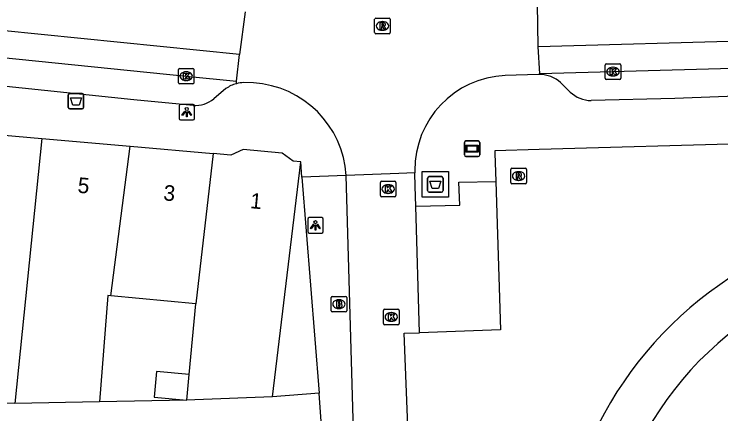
# Model space of a CAD drawing. Extents: x 162250 to 162654, y 380744 to 381605.
# Drawn here: x 162347.75 to 162393.23, y 381182.3 to 381208.05 of the extents above; entities that cross this region are included whole.
import ezdxf

# ---------------------------------------------------------------- set-up
doc = ezdxf.new("R2010")
doc.units = 0
for name, color, linetype in [('IMGEO_Afval_apart_plaats', 7, 'Continuous'), ('IMGEO_Afvalbak', 7, 'Continuous'), ('IMGEO_Brandkraan', 7, 'Continuous'), ('IMGEO_Kolk', 7, 'Continuous'), ('IMGEO_Lichtpunt', 7, 'Continuous'), ('IMGEO_Pand', 7, 'Continuous'), ('IMGEO_Pand_nummerreeks', 7, 'Continuous'), ('IMGEO_Parkeervlak_open', 7, 'Continuous'), ('IMGEO_Reclamebord', 7, 'Continuous'), ('IMGEO_Rijbaan_lokaal_gesloten', 7, 'Continuous'), ('IMGEO_Rioolput', 7, 'Continuous'), ('IMGEO_Voetpad_gesloten', 7, 'Continuous'), ('IMGEO_Voetpad_open', 7, 'Continuous'), ('IMGEO_Woonerf_open', 7, 'Continuous')]:
    doc.layers.add(name, color=color, linetype=linetype)

msp = doc.modelspace()

# ---------------------------------------------------------------- linework, layer by layer
at = {"layer": 'IMGEO_Afval_apart_plaats'}
for p, q in [((162374.461, 381197.584), (162375.251, 381197.584)), ((162375.251, 381197.584), (162374.461, 381197.584)), ((162374.361, 381196.684), (162374.361, 381197.484)), ((162374.361, 381197.484), (162374.361, 381196.684)), ((162375.351, 381197.484), (162375.351, 381196.684)), ((162375.351, 381196.684), (162375.351, 381197.484)), ((162375.251, 381196.584), (162374.461, 381196.584)), ((162374.461, 381196.584), (162375.251, 381196.584))]:
    msp.add_line(p, q, dxfattribs=at)
msp.add_lwpolyline([(162374.504, 381197.298), (162375.208, 381197.298), (162375.059, 381196.828), (162374.653, 381196.828), (162374.504, 381197.298)], dxfattribs=at)
for centre, start, end in [((162374.461, 381197.484), 90, 180), ((162374.461, 381197.484), 90, 180), ((162375.251, 381197.484), 0, 90), ((162375.251, 381197.484), 360, 90), ((162374.461, 381196.684), 180, 270), ((162374.461, 381196.684), 180, 270), ((162375.251, 381196.684), 270, 0), ((162375.251, 381196.684), 270, 0)]:
    msp.add_arc(centre, 0.1, start, end, dxfattribs=at)
at = {"layer": 'IMGEO_Afvalbak'}
for p, q in [((162351.23, 381202.041), (162351.23, 381202.841)), ((162351.23, 381202.841), (162351.23, 381202.041)), ((162351.33, 381202.941), (162352.12, 381202.941)), ((162352.12, 381202.941), (162351.33, 381202.941)), ((162352.22, 381202.841), (162352.22, 381202.041)), ((162352.22, 381202.041), (162352.22, 381202.841)), ((162352.12, 381201.941), (162351.33, 381201.941)), ((162351.33, 381201.941), (162352.12, 381201.941))]:
    msp.add_line(p, q, dxfattribs=at)
msp.add_lwpolyline([(162351.373, 381202.655), (162352.077, 381202.655), (162351.928, 381202.185), (162351.522, 381202.185), (162351.373, 381202.655)], dxfattribs=at)
for centre, start, end in [((162351.33, 381202.841), 90, 180), ((162351.33, 381202.841), 90, 180), ((162352.12, 381202.841), 0, 90), ((162352.12, 381202.841), 360, 90), ((162351.33, 381202.041), 180, 270), ((162351.33, 381202.041), 180, 270), ((162352.12, 381202.041), 270, 0), ((162352.12, 381202.041), 270, 0)]:
    msp.add_arc(centre, 0.1, start, end, dxfattribs=at)
at = {"layer": 'IMGEO_Brandkraan'}
for p, q in [((162368.148, 381188.942), (162368.148, 381189.794)), ((162368.223, 381189.868), (162369.075, 381189.868)), ((162369.149, 381189.794), (162369.149, 381188.942)), ((162368.636, 381189.648), (162368.661, 381189.648)), ((162368.659, 381189.088), (162368.634, 381189.088)), ((162369.075, 381188.868), (162368.223, 381188.868))]:
    msp.add_line(p, q, dxfattribs=at)
for points in [[(162368.148, 381188.942), (162368.148, 381189.794)], [(162368.223, 381189.868), (162369.075, 381189.868)], [(162369.149, 381189.794), (162369.149, 381188.942)], [(162368.496, 381189.568), (162368.496, 381189.168), (162368.709, 381189.168)], [(162368.727, 381189.568), (162368.496, 381189.568)], [(162368.675, 381189.487), (162368.621, 381189.487), (162368.621, 381189.411)], [(162368.621, 381189.411), (162368.674, 381189.411)], [(162368.683, 381189.335), (162368.621, 381189.335), (162368.621, 381189.254)], [(162368.621, 381189.254), (162368.683, 381189.254)], [(162369.075, 381188.868), (162368.223, 381188.868)]]:
    msp.add_lwpolyline(points, dxfattribs=at)
for centre, radius, start, end in [((162368.225, 381189.792), 0.0765, 91.552, 178.448), ((162368.225, 381189.792), 0.0765, 91.552, 178.448), ((162369.073, 381189.792), 0.0765, 1.552, 88.448), ((162369.073, 381189.792), 0.0765, 1.552, 88.448), ((162368.676, 381189.449), 0.0379, 267.8285, 90.9355), ((162368.684, 381189.294), 0.0404, 269.8759, 90.5077), ((162368.731, 381189.423), 0.145, 59.4692, 91.5367), ((162368.756, 381189.47), 0.0922, 285.5137, 58.1501), ((162368.761, 381189.278), 0.105, 301.3115, 78.989), ((162368.225, 381188.944), 0.0765, 181.552, 268.448), ((162368.225, 381188.944), 0.0765, 181.552, 268.448), ((162368.715, 381189.419), 0.251, 268.6676, 293.5347), ((162369.073, 381188.944), 0.0765, 271.552, 358.448), ((162369.073, 381188.944), 0.0765, 271.552, 358.448)]:
    msp.add_arc(centre, radius, start, end, dxfattribs=at)
for centre, major_axis, ratio, start_param, end_param in [((162368.635, 381189.368), (-0.387, 0.002), 0.722429, 4.712389, 7.853982), ((162368.66, 381189.368), (-0.39, 0.002), 0.717154, 1.570796, 4.712389)]:
    msp.add_ellipse(centre, major_axis=major_axis, ratio=ratio, start_param=start_param, end_param=end_param, dxfattribs=at)
at = {"layer": 'IMGEO_Kolk'}
for p, q in [((162385.861, 381204.847), (162386.713, 381204.847)), ((162358.322, 381203.627), (162358.322, 381204.479)), ((162358.397, 381204.553), (162359.249, 381204.553)), ((162359.323, 381204.479), (162359.323, 381203.627)), ((162385.786, 381203.921), (162385.786, 381204.773)), ((162386.274, 381204.627), (162386.299, 381204.627)), ((162386.787, 381204.773), (162386.787, 381203.921)), ((162358.81, 381204.333), (162358.835, 381204.333)), ((162386.297, 381204.067), (162386.272, 381204.067)), ((162359.249, 381203.553), (162358.397, 381203.553)), ((162358.833, 381203.773), (162358.808, 381203.773)), ((162386.713, 381203.847), (162385.861, 381203.847)), ((162371.321, 381196.357), (162371.321, 381197.209)), ((162371.396, 381197.283), (162372.248, 381197.283)), ((162371.809, 381197.063), (162371.834, 381197.063)), ((162372.322, 381197.209), (162372.322, 381196.357)), ((162372.248, 381196.283), (162371.396, 381196.283)), ((162371.832, 381196.503), (162371.807, 381196.503)), ((162371.517, 381188.116), (162371.517, 381188.968)), ((162371.592, 381189.042), (162372.444, 381189.042)), ((162372.518, 381188.968), (162372.518, 381188.116)), ((162372.005, 381188.822), (162372.03, 381188.822)), ((162372.444, 381188.042), (162371.592, 381188.042)), ((162372.028, 381188.262), (162372.003, 381188.262))]:
    msp.add_line(p, q, dxfattribs=at)
for points in [[(162385.861, 381204.847), (162386.713, 381204.847)], [(162358.322, 381203.627), (162358.322, 381204.479)], [(162358.397, 381204.553), (162359.249, 381204.553)], [(162359.323, 381204.479), (162359.323, 381203.627)], [(162385.786, 381203.921), (162385.786, 381204.773)], [(162386.107, 381204.547), (162386.23, 381204.547), (162386.23, 381204.396), (162386.36, 381204.547), (162386.524, 381204.547), (162386.378, 381204.396), (162386.531, 381204.147), (162386.379, 381204.147), (162386.294, 381204.311), (162386.23, 381204.244), (162386.23, 381204.147), (162386.107, 381204.147), (162386.107, 381204.547)], [(162386.787, 381204.773), (162386.787, 381203.921)], [(162358.643, 381204.253), (162358.766, 381204.253), (162358.766, 381204.102), (162358.896, 381204.253), (162359.06, 381204.253), (162358.914, 381204.102), (162359.067, 381203.853), (162358.915, 381203.853), (162358.83, 381204.017), (162358.766, 381203.95), (162358.766, 381203.853), (162358.643, 381203.853), (162358.643, 381204.253)], [(162359.249, 381203.553), (162358.397, 381203.553)], [(162386.713, 381203.847), (162385.861, 381203.847)], [(162371.321, 381196.357), (162371.321, 381197.209)], [(162371.396, 381197.283), (162372.248, 381197.283)], [(162372.322, 381197.209), (162372.322, 381196.357)], [(162371.642, 381196.983), (162371.765, 381196.983), (162371.765, 381196.832), (162371.895, 381196.983), (162372.059, 381196.983), (162371.913, 381196.832), (162372.066, 381196.583), (162371.914, 381196.583), (162371.829, 381196.747), (162371.765, 381196.68), (162371.765, 381196.583), (162371.642, 381196.583), (162371.642, 381196.983)], [(162372.248, 381196.283), (162371.396, 381196.283)], [(162371.517, 381188.116), (162371.517, 381188.968)], [(162371.592, 381189.042), (162372.444, 381189.042)], [(162372.518, 381188.968), (162372.518, 381188.116)], [(162371.838, 381188.742), (162371.961, 381188.742), (162371.961, 381188.591), (162372.091, 381188.742), (162372.255, 381188.742), (162372.109, 381188.591), (162372.262, 381188.342), (162372.11, 381188.342), (162372.025, 381188.506), (162371.961, 381188.439), (162371.961, 381188.342), (162371.838, 381188.342), (162371.838, 381188.742)], [(162372.444, 381188.042), (162371.592, 381188.042)]]:
    msp.add_lwpolyline(points, dxfattribs=at)
for centre, start, end in [((162385.863, 381204.771), 91.552, 178.448), ((162385.863, 381204.771), 91.552, 178.448), ((162386.711, 381204.771), 1.552, 88.448), ((162386.711, 381204.771), 1.552, 88.448), ((162358.399, 381204.477), 91.552, 178.448), ((162358.399, 381204.477), 91.552, 178.448), ((162359.247, 381204.477), 1.552, 88.448), ((162359.247, 381204.477), 1.552, 88.448), ((162385.863, 381203.923), 181.552, 268.448), ((162385.863, 381203.923), 181.552, 268.448), ((162386.711, 381203.923), 271.552, 358.448), ((162386.711, 381203.923), 271.552, 358.448), ((162358.399, 381203.629), 181.552, 268.448), ((162358.399, 381203.629), 181.552, 268.448), ((162359.247, 381203.629), 271.552, 358.448), ((162359.247, 381203.629), 271.552, 358.448), ((162371.398, 381197.207), 91.552, 178.448), ((162371.398, 381197.207), 91.552, 178.448), ((162372.246, 381197.207), 1.552, 88.448), ((162372.246, 381197.207), 1.552, 88.448), ((162371.398, 381196.359), 181.552, 268.448), ((162371.398, 381196.359), 181.552, 268.448), ((162372.246, 381196.359), 271.552, 358.448), ((162372.246, 381196.359), 271.552, 358.448), ((162371.594, 381188.966), 91.552, 178.448), ((162371.594, 381188.966), 91.552, 178.448), ((162372.442, 381188.966), 1.552, 88.448), ((162372.442, 381188.966), 1.552, 88.448), ((162371.594, 381188.118), 181.552, 268.448), ((162371.594, 381188.118), 181.552, 268.448), ((162372.442, 381188.118), 271.552, 358.448), ((162372.442, 381188.118), 271.552, 358.448)]:
    msp.add_arc(centre, 0.0765, start, end, dxfattribs=at)
for centre, major_axis, ratio, start_param, end_param in [((162386.273, 381204.347), (-0.387, 0.002), 0.722429, 4.712389, 7.853982), ((162386.298, 381204.347), (-0.39, 0.002), 0.717154, 1.570796, 4.712389), ((162358.809, 381204.053), (-0.387, 0.002), 0.722429, 4.712389, 7.853982), ((162358.834, 381204.053), (-0.39, 0.002), 0.717154, 1.570796, 4.712389), ((162371.808, 381196.783), (-0.387, 0.002), 0.722429, 4.712389, 7.853982), ((162371.833, 381196.783), (-0.39, 0.002), 0.717154, 1.570796, 4.712389), ((162372.004, 381188.542), (-0.387, 0.002), 0.722429, 4.712389, 7.853982), ((162372.029, 381188.542), (-0.39, 0.002), 0.717154, 1.570796, 4.712389)]:
    msp.add_ellipse(centre, major_axis=major_axis, ratio=ratio, start_param=start_param, end_param=end_param, dxfattribs=at)
at = {"layer": 'IMGEO_Lichtpunt'}
for p, q in [((162358.359, 381202.144), (162358.359, 381201.337)), ((162358.359, 381202.144), (162358.359, 381201.337)), ((162359.261, 381202.239), (162358.453, 381202.239)), ((162359.261, 381202.239), (162358.453, 381202.239)), ((162359.355, 381201.337), (162359.355, 381202.144)), ((162359.355, 381201.337), (162359.355, 381202.144)), ((162358.453, 381201.243), (162359.261, 381201.243)), ((162358.453, 381201.243), (162359.261, 381201.243)), ((162366.64, 381194.85), (162366.64, 381194.043)), ((162366.64, 381194.85), (162366.64, 381194.043)), ((162367.542, 381194.945), (162366.734, 381194.945)), ((162367.542, 381194.945), (162366.734, 381194.945)), ((162367.636, 381194.043), (162367.636, 381194.85)), ((162367.636, 381194.043), (162367.636, 381194.85)), ((162366.734, 381193.949), (162367.542, 381193.949)), ((162366.734, 381193.949), (162367.542, 381193.949))]:
    msp.add_line(p, q, dxfattribs=at)
for points in [[(162358.733, 381201.808), (162358.772, 381201.78), (162358.584, 381201.518), (162358.546, 381201.545), (162358.733, 381201.808)], [(162358.835, 381201.76), (162358.882, 381201.76), (162358.882, 381201.438), (162358.835, 381201.438), (162358.835, 381201.76)], [(162358.945, 381201.78), (162358.983, 381201.807), (162359.17, 381201.545), (162359.131, 381201.517), (162358.945, 381201.78)], [(162367.014, 381194.514), (162367.053, 381194.486), (162366.865, 381194.224), (162366.827, 381194.251), (162367.014, 381194.514)], [(162367.116, 381194.466), (162367.163, 381194.466), (162367.163, 381194.144), (162367.116, 381194.144), (162367.116, 381194.466)], [(162367.226, 381194.486), (162367.264, 381194.513), (162367.451, 381194.251), (162367.412, 381194.223), (162367.226, 381194.486)]]:
    msp.add_lwpolyline(points, dxfattribs=at)
for centre in [(162358.858, 381201.942), (162367.139, 381194.648)]:
    msp.add_circle(centre, 0.0994, dxfattribs=at)
for centre, start, end in [((162358.453, 381202.144), 90, 180), ((162358.453, 381202.144), 90, 180), ((162359.261, 381202.144), 0, 90), ((162359.261, 381202.144), 0, 90), ((162358.453, 381201.337), 180, 270), ((162358.453, 381201.337), 180, 270), ((162359.261, 381201.337), 270, 0), ((162359.261, 381201.337), 270, 360), ((162366.734, 381194.85), 90, 180), ((162366.734, 381194.85), 90, 180), ((162367.542, 381194.85), 0, 90), ((162367.542, 381194.85), 0, 90), ((162366.734, 381194.043), 180, 270), ((162366.734, 381194.043), 180, 270), ((162367.542, 381194.043), 270, 0), ((162367.542, 381194.043), 270, 360)]:
    msp.add_arc(centre, 0.0946, start, end, dxfattribs=at)
at = {"layer": 'IMGEO_Pand'}
for points in [[(162344.185, 381200.52), (162349.528, 381200.046)], [(162349.528, 381200.046), (162347.792, 381182.966)], [(162349.528, 381200.046), (162355.226, 381199.54)], [(162353.981, 381189.903), (162355.226, 381199.54)], [(162355.226, 381199.54), (162360.555, 381199.068)], [(162360.555, 381199.068), (162359.44, 381189.386)], [(162366.19, 381198.541), (162365.705, 381198.587), (162364.991, 381199.094), (162362.485, 381199.331), (162361.691, 381198.967), (162360.555, 381199.068)], [(162364.374, 381183.398), (162366.19, 381198.541)], [(162353.981, 381189.903), (162353.771, 381189.923), (162353.232, 381183.071)], [(162359.44, 381189.386), (162353.981, 381189.903)], [(162359.013, 381184.831), (162359.44, 381189.386)], [(162359.013, 381184.831), (162356.905, 381185.029), (162356.75, 381183.375), (162358.859, 381183.183)], [(162358.859, 381183.183), (162359.013, 381184.831)], [(162347.792, 381182.966), (162342.165, 381183.123)], [(162353.232, 381183.071), (162347.792, 381182.966)], [(162364.374, 381183.398), (162359.378, 381183.203), (162358.859, 381183.183)]]:
    msp.add_lwpolyline(points, dxfattribs=at)
at = {"layer": 'IMGEO_Parkeervlak_open'}
for points in [[(162378.745, 381197.276), (162379.047, 381187.724), (162373.842, 381187.531)], [(162373.842, 381187.531), (162373.596, 381195.687)]]:
    msp.add_lwpolyline(points, dxfattribs=at)
at = {"layer": 'IMGEO_Reclamebord'}
for p, q in [((162376.825, 381199.881), (162377.615, 381199.881)), ((162377.615, 381199.881), (162376.825, 381199.881)), ((162376.725, 381198.981), (162376.725, 381199.781)), ((162376.725, 381199.781), (162376.725, 381198.981)), ((162377.715, 381199.781), (162377.715, 381198.981)), ((162377.715, 381198.981), (162377.715, 381199.781)), ((162377.615, 381198.881), (162376.825, 381198.881)), ((162376.825, 381198.881), (162377.615, 381198.881))]:
    msp.add_line(p, q, dxfattribs=at)
for points in [[(162376.826, 381199.613), (162377.614, 381199.613), (162377.614, 381199.149), (162376.826, 381199.149), (162376.826, 381199.613)], [(162376.891, 381199.548), (162376.891, 381199.214), (162377.549, 381199.214), (162377.549, 381199.548), (162376.891, 381199.548)]]:
    msp.add_lwpolyline(points, dxfattribs=at)
for centre, start, end in [((162376.825, 381199.781), 90, 180), ((162376.825, 381199.781), 90, 180), ((162377.615, 381199.781), 0, 90), ((162377.615, 381199.781), 360, 90), ((162376.825, 381198.981), 180, 270), ((162376.825, 381198.981), 180, 270), ((162377.615, 381198.981), 270, 0), ((162377.615, 381198.981), 270, 0)]:
    msp.add_arc(centre, 0.1, start, end, dxfattribs=at)
at = {"layer": 'IMGEO_Rijbaan_lokaal_gesloten'}
for points in [[(162362.253, 381205.457), (162329.041, 381208.801), (162327.697, 381208.936)], [(162381.477, 381205.975), (162381.43, 381208.683)], [(162362.607, 381208.202), (162362.253, 381205.457)], [(162381.477, 381205.975), (162409.05, 381206.74), (162411.31, 381206.802), (162453.911, 381207.983)], [(162325.166, 381207.213), (162334.8, 381206.462), (162345.523, 381205.417), (162358.828, 381204.054), (162362.066, 381203.727)], [(162381.577, 381204.213), (162381.477, 381205.975)], [(162362.066, 381203.727), (162362.253, 381205.457)], [(162409.861, 381205.082), (162401.103, 381204.745), (162399.402, 381204.708), (162381.577, 381204.213)], [(162381.579, 381204.167), (162381.515, 381204.168), (162381.488, 381204.167), (162379.35, 381204.095)], [(162381.577, 381204.213), (162381.579, 381204.167)], [(162362.049, 381203.571), (162362.066, 381203.727)], [(162363.148, 381203.617), (162362.523, 381203.642)], [(162373.543, 381197.824), (162372.496, 381197.784), (162369.115, 381197.654)], [(162373.541, 381197.966), (162373.543, 381197.824)]]:
    msp.add_lwpolyline(points, dxfattribs=at)
for centre, radius, start, end in [((162379.607, 381198.034), 6.067, 92.4325, 180.6384), ((162362.597, 381201.532), 2.111, 92.0002, 105.0377), ((162362.775, 381197.277), 6.351, 3.4038, 86.6346)]:
    msp.add_arc(centre, radius, start, end, dxfattribs=at)
at = {"layer": 'IMGEO_Rioolput'}
for p, q in [((162370.95, 381206.863), (162370.95, 381207.715)), ((162371.025, 381207.789), (162371.877, 381207.789)), ((162371.438, 381207.569), (162371.463, 381207.569)), ((162371.951, 381207.715), (162371.951, 381206.863)), ((162371.877, 381206.789), (162371.025, 381206.789)), ((162371.461, 381207.009), (162371.436, 381207.009)), ((162379.713, 381197.195), (162379.713, 381198.047)), ((162379.788, 381198.121), (162380.64, 381198.121)), ((162380.714, 381198.047), (162380.714, 381197.195)), ((162380.201, 381197.901), (162380.226, 381197.901)), ((162380.64, 381197.121), (162379.788, 381197.121)), ((162380.224, 381197.341), (162380.199, 381197.341))]:
    msp.add_line(p, q, dxfattribs=at)
for points in [[(162370.95, 381206.863), (162370.95, 381207.715)], [(162371.025, 381207.789), (162371.877, 381207.789)], [(162371.951, 381207.715), (162371.951, 381206.863)], [(162371.539, 381207.487), (162371.287, 381207.489), (162371.287, 381207.089)], [(162371.287, 381207.089), (162371.411, 381207.089), (162371.411, 381207.251), (162371.422, 381207.251)], [(162371.465, 381207.408), (162371.411, 381207.408), (162371.411, 381207.327)], [(162371.411, 381207.327), (162371.463, 381207.327)], [(162371.469, 381207.222), (162371.54, 381207.089), (162371.68, 381207.089), (162371.615, 381207.215)], [(162371.877, 381206.789), (162371.025, 381206.789)], [(162379.713, 381197.195), (162379.713, 381198.047)], [(162379.788, 381198.121), (162380.64, 381198.121)], [(162380.714, 381198.047), (162380.714, 381197.195)], [(162380.302, 381197.819), (162380.05, 381197.821), (162380.05, 381197.421)], [(162380.05, 381197.421), (162380.174, 381197.421), (162380.174, 381197.583), (162380.185, 381197.583)], [(162380.228, 381197.74), (162380.174, 381197.74), (162380.174, 381197.659)], [(162380.174, 381197.659), (162380.226, 381197.659)], [(162380.232, 381197.554), (162380.303, 381197.421), (162380.443, 381197.421), (162380.378, 381197.547)], [(162380.64, 381197.121), (162379.788, 381197.121)]]:
    msp.add_lwpolyline(points, dxfattribs=at)
for centre, radius, start, end in [((162371.027, 381207.713), 0.0765, 91.552, 178.448), ((162371.027, 381207.713), 0.0765, 91.552, 178.448), ((162371.875, 381207.713), 0.0765, 1.552, 88.448), ((162371.875, 381207.713), 0.0765, 1.552, 88.448), ((162371.421, 381207.198), 0.0533, 26.0293, 88.6989), ((162371.447, 381207.516), 0.19, 274.7715, 282.9687), ((162371.471, 381207.312), 0.0964, 77.0061, 93.1865), ((162371.485, 381207.369), 0.0378, 276.6634, 79.6772), ((162371.538, 381207.377), 0.109, 350.3612, 89.416), ((162371.536, 381207.377), 0.112, 277.5842, 350.9817), ((162371.52, 381207.162), 0.108, 29.5134, 73.7905), ((162371.027, 381206.865), 0.0765, 181.552, 268.448), ((162371.027, 381206.865), 0.0765, 181.552, 268.448), ((162371.875, 381206.865), 0.0765, 271.552, 358.448), ((162371.875, 381206.865), 0.0765, 271.552, 358.448), ((162379.79, 381198.045), 0.0765, 91.552, 178.448), ((162379.79, 381198.045), 0.0765, 91.552, 178.448), ((162380.638, 381198.045), 0.0765, 1.552, 88.448), ((162380.638, 381198.045), 0.0765, 1.552, 88.448), ((162380.184, 381197.53), 0.0533, 26.0293, 88.6989), ((162380.21, 381197.848), 0.19, 274.7715, 282.9687), ((162380.234, 381197.644), 0.0964, 77.0061, 93.1865), ((162380.248, 381197.701), 0.0378, 276.6634, 79.6772), ((162380.301, 381197.709), 0.109, 350.3612, 89.416), ((162380.299, 381197.709), 0.112, 277.5842, 350.9817), ((162380.283, 381197.494), 0.108, 29.5134, 73.7905), ((162379.79, 381197.197), 0.0765, 181.552, 268.448), ((162379.79, 381197.197), 0.0765, 181.552, 268.448), ((162380.638, 381197.197), 0.0765, 271.552, 358.448), ((162380.638, 381197.197), 0.0765, 271.552, 358.448)]:
    msp.add_arc(centre, radius, start, end, dxfattribs=at)
for centre, major_axis, ratio, start_param, end_param in [((162371.437, 381207.289), (-0.387, 0.002), 0.722429, 4.712389, 7.853982), ((162371.462, 381207.289), (-0.39, 0.002), 0.717154, 1.570796, 4.712389), ((162380.2, 381197.621), (-0.387, 0.002), 0.722429, 4.712389, 7.853982), ((162380.225, 381197.621), (-0.39, 0.002), 0.717154, 1.570796, 4.712389)]:
    msp.add_ellipse(centre, major_axis=major_axis, ratio=ratio, start_param=start_param, end_param=end_param, dxfattribs=at)
at = {"layer": 'IMGEO_Voetpad_gesloten'}
msp.add_lwpolyline([(162375.695, 381197.912), (162375.704, 381196.266), (162374.017, 381196.257), (162374.008, 381197.903), (162375.695, 381197.912)], dxfattribs=at)
at = {"layer": 'IMGEO_Voetpad_open'}
for points in [[(162359.273, 381202.174), (162355.455, 381202.53), (162327.715, 381205.435)], [(162383.532, 381203.03), (162382.916, 381203.636)], [(162361.382, 381203.253), (162360.593, 381202.585)], [(162406.852, 381203.169), (162399.837, 381202.991), (162390.26, 381202.607), (162384.889, 381202.479)], [(162402.283, 381199.926), (162402.223, 381199.924), (162401.413, 381199.901), (162395.289, 381199.722), (162381.546, 381199.321), (162378.682, 381199.237), (162378.687, 381199.073), (162378.744, 381197.293), (162378.745, 381197.276)], [(162366.269, 381197.545), (162366.19, 381198.541)], [(162369.115, 381197.654), (162366.269, 381197.545)], [(162366.269, 381197.545), (162367.369, 381183.635)], [(162371.488, 381120.602), (162370.442, 381153.711), (162372.814, 381153.789), (162372.262, 381170.102), (162369.918, 381170.032), (162369.115, 381197.654)], [(162373.596, 381195.687), (162373.558, 381196.953), (162373.543, 381197.824)], [(162373.596, 381195.687), (162376.434, 381195.748), (162376.37, 381197.227), (162378.745, 381197.276)], [(162367.369, 381183.635), (162364.374, 381183.398)], [(162367.515, 381181.772), (162367.514, 381181.806), (162367.369, 381183.635)], [(162358.859, 381183.183), (162353.232, 381183.071)]]:
    msp.add_lwpolyline(points, dxfattribs=at)
for centre, radius, start, end in [((162381.541, 381202.123), 2.044, 47.7396, 88.9386), ((162362.585, 381201.587), 2.055, 105.1323, 125.8478), ((162384.928, 381204.522), 2.043, 226.9008, 268.9007), ((162359.386, 381204.137), 1.966, 266.7129, 307.8765), ((162407.245, 381170.506), 24.557, 123.109, 182.9344), ((162407.113, 381170.744), 21.382, 113.3729, 183.8578)]:
    msp.add_arc(centre, radius, start, end, dxfattribs=at)
at = {"layer": 'IMGEO_Woonerf_open'}
msp.add_lwpolyline([(162375.911, 381168.88), (162375.907, 381169.266), (162375.553, 381178.828), (162373.184, 381178.813), (162372.856, 381187.495), (162373.842, 381187.531)], dxfattribs=at)

# ---------------------------------------------------------------- texts
at = {"layer": 'IMGEO_Pand_nummerreeks'}
for s, rotation, p in [('5', 354.9311, (162351.807, 381196.55)), ('3', 354.9311, (162357.326, 381196.06)), ('1', 354.66, (162362.906, 381195.554))]:
    msp.add_text(s, height=1, rotation=rotation, dxfattribs=at).set_placement(p)

doc.saveas('drawing.dxf')
